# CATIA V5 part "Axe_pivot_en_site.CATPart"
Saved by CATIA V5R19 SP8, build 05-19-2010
Part number: Axe_pivot_en_site
Bounding box of the stored display mesh (mm): x -180 to 175, y 283.773 to 312.773, z 1387.428 to 1412.542
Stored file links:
  G:\EU_thinkMotion\CFAO_2010\MMS_groupe2\MMS_groupe2\OK\nrosalie\nrosalie_cfao_support_d_arme_legere_final\Axe_pivot_en_site.CATPart
  G:\EU_thinkMotion\CFAO_2010\MMS_groupe2\MMS_groupe2\OK\nrosalie\nrosalie_cfao_support_d_arme_legere_final\nrosalie_Support_d_arme_legere.CATProduct
  G:\EU_thinkMotion\CFAO_2010\MMS_groupe2\MMS_groupe2\OK\nrosalie\nrosalie_cfao_support_d_arme_legere_final\Squelette_piece_support.CATPart
  C:\Espace travail\Cours 2A MMS\CFAO\Projet CFAO\Modele CAO\Version_finale_sans_siege\Symmetry of Piece_de_support.CATPart
  G:\EU_thinkMotion\CFAO_2010\MMS_groupe2\MMS_groupe2\OK\nrosalie\nrosalie_cfao_support_d_arme_legere_final\Piece_de_support.CATPart
  G:\EU_thinkMotion\CFAO_2010\MMS_groupe2\MMS_groupe2\OK\nrosalie\nrosalie_cfao_support_d_arme_legere_final\Bras.CATPart
  G:\EU_thinkMotion\CFAO_2010\MMS_groupe2\MMS_groupe2\OK\nrosalie\nrosalie_cfao_support_d_arme_legere_final\Axe_pivot_en_site_2.CATPart
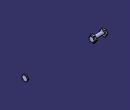
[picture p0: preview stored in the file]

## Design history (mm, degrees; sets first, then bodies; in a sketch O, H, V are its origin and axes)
Set1
  Plane1 "Interphase_pivot_permettant _la_rotation_en_site": linked copy from another document
  DatumSurface1: linked copy from another document
  Point1 "Centre_de_la_pivot": linked copy from another document
  DatumCurve1: linked copy from another document
  Point2 "Centre_cou_du_servant": linked copy from another document
  DatumCurve2: linked copy from another document
  DatumSurface2: linked copy from another document
  Sketch1, origin (130, 0, 0), H (0, -1, 0), V (0, 0, 1), geometry linked from another document
  DatumSurface3: linked copy from another document
  DatumCurve3: linked copy from another document
  DatumSurface4: linked copy from another document
Body1 (main body)
  Sketch2 on Plane1, origin (-150, 0, 0), H (0, 1, 0), V (0, 0, 1)
    projected circle E1 centre (298.2728, 1399.9851) radius 7.5 from edge of DatumCurve2
  Pad1: profile Sketch2, direction (1, 0, 0), up to face of DatumSurface3, offset 10, opposite side up to face of DatumSurface1
  Chamfer1: length 1, angle 45, on edge [face of Pad1 from Sketch2.E1 | end face of Pad1]
  Sketch3 on end face of Pad1, origin (-180, 0, 0), H (0, 1, 0), V (0, 0, 1)
    circle A1 centre (298.2728, 1399.9851) radius 7.5
    construction circle A2 centre (298.2728, 1399.9851) radius 14.5
    point P2 (298.2728, 1399.9851)
    line L1 (291.0228, 1412.5425) -> (305.5228, 1412.5425)
    point P3 (291.0228, 1412.5425)
    point P4 (305.5228, 1412.5425)
    line L2 (305.5228, 1412.5425) -> (312.7728, 1399.9851)
    point P5 (312.7728, 1399.9851)
    line L3 (312.7728, 1399.9851) -> (305.5228, 1387.4277)
    point P6 (305.5228, 1387.4277)
    line L4 (305.5228, 1387.4277) -> (291.0228, 1387.4277)
    point P7 (291.0228, 1387.4277)
    line L5 (291.0228, 1387.4277) -> (283.7728, 1399.9851)
    point P8 (283.7728, 1399.9851)
    line L6 (291.0228, 1412.5425) -> (283.7728, 1399.9851)
    point P9 (291.0228, 1412.5425)
    construction line L7 (244.7645, 1399.9851) -> (302.6837, 1399.9851)
    axis line L8 (298.2728, 1399.9851) -> (313.4612, 1426.2922)
    reference projected circle E1 centre (298.2728, 1399.9851) radius 7.5 from edge of DatumCurve3
    angle L8 L7 = 60
    distance A1 A2 = 7
    concentricity: A2 A1
    coincidence: P3 A2, P4 A2, P5 A2, P6 A2, P7 A2, P8 A2, P9 A2, L7 P2, P8 L7, P4 L8, P5 L7, P9 P3, E1 A1
    horizontal: L1 H, L4 H, L7 H
    symmetry: L1 L4 L7
  Pad2: profile Sketch3, direction (1, 0, 0), length 10, opposite side length -3
  Sketch4 on start face of Pad1, origin (-130, 0, 0), H (0, 1, 0), V (0, 0, 1)
    construction circle A1 centre (298.2728, 1399.9851) radius 14.5
    point P1 (298.2728, 1399.9851)
    reference projected point E1 (305.5228, 1412.5425) from vertex [element of Sketch3 | element of Sketch3]
    construction line L1 (334.4018, 1399.9851) -> (270.9553, 1399.9851)
    construction line L2 (298.2728, 1433.6771) -> (298.2728, 1377.3514)
    axis line L3 (298.2728, 1399.9851) -> (319.4834, 1436.7229)
    point P6 (298.2728, 1399.9851)
    line L4 (291.0228, 1412.5425) -> (305.5228, 1412.5425)
    point P8 (291.0228, 1412.5425)
    point P9 (305.5228, 1412.5425)
    line L5 (312.7728, 1399.9851) -> (305.5228, 1412.5425)
    point P10 (312.7728, 1399.9851)
    line L6 (312.7728, 1399.9851) -> (305.5228, 1387.4277)
    point P11 (312.7728, 1399.9851)
    point P12 (305.5228, 1387.4277)
    line L7 (305.5228, 1387.4277) -> (291.0228, 1387.4277)
    point P13 (291.0228, 1387.4277)
    line L8 (291.0228, 1387.4277) -> (283.7728, 1399.9851)
    point P14 (283.7728, 1399.9851)
    line L9 (283.7728, 1399.9851) -> (291.0228, 1412.5425)
    reference projected circle E2 centre (298.2728, 1399.9851) radius 7.5 from edge [face of Pad1 from Sketch2.E1 | start face of Pad1]
    angle L3 L1 = 60
    coincidence: A1 E1, L1 P1, L2 P1, P6 L1, P6 P1, P8 A1, P9 L3, P9 A1, P10 L1, P10 A1, P11 L5, P11 A1, P12 A1, P13 A1, P14 L1, P14 A1, P10 P11
    horizontal: L1 H
    vertical: L2 V
    parallelism: L7 L4
    symmetry: L4 L7 L1
    concentricity: A1 E2
  Pad3: profile Sketch4, direction (1, 0, 0), length 10
  Fillet1: radius 2.5, on edge [face of Pad3 from Sketch4.L4 | end face of Pad3]; end face of Pad3
  Sketch5 on face of DatumSurface2, origin (170, 0, 0), H (0, -1, 0), V (0, 0, 1)
  Pad4: profile Sketch5, direction (1, 0, 0), length 5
